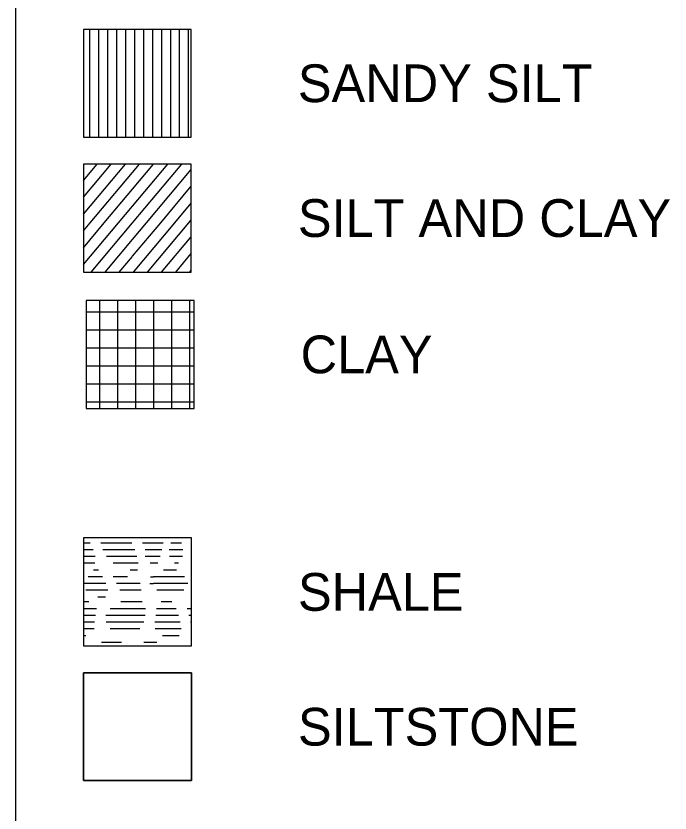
# Model space of a CAD drawing. Extents: x -60 to 375, y -195 to 44.
# Drawn here: x 6.309 to 7.521, y 8.242 to 9.72 of the extents above; entities that cross this region are included whole.
import ezdxf

# ---------------------------------------------------------------- set-up
doc = ezdxf.new("R2010")
doc.units = 0
for name, color, linetype in [('GM_X_County', 7, 'Continuous'), ('GM_X_Minor_Lake_Text', 7, 'Continuous'), ('GM_X_Minor_River_Text', 7, 'Continuous')]:
    doc.layers.add(name, color=color, linetype=linetype)

msp = doc.modelspace()

# ---------------------------------------------------------------- linework, layer by layer
at = {"layer": 'GM_X_Minor_Lake_Text'}
msp.add_line((6.3089, 5.5693), (6.3089, 10.7192), dxfattribs=at)
for points in [[(6.4339, 9.4954), (6.6339, 9.4954), (6.6339, 9.6954), (6.4339, 9.6954)], [(6.4339, 9.2454), (6.6339, 9.2454), (6.6339, 9.4454), (6.4339, 9.4454)], [(6.439, 8.9926), (6.639, 8.9926), (6.639, 9.1926), (6.439, 9.1926)], [(6.4341, 8.5522), (6.6341, 8.5522), (6.6341, 8.7522), (6.4341, 8.7522)], [(6.4341, 8.3022), (6.6341, 8.3022), (6.6341, 8.5022), (6.4341, 8.5022)]]:
    msp.add_lwpolyline(points, close=True, dxfattribs=at)
at = {"layer": 'GM_X_Minor_River_Text'}
for p, q in [((6.4457, 9.5985), (6.4457, 9.6954)), ((6.4623, 9.5985), (6.4623, 9.6954)), ((6.479, 9.5985), (6.479, 9.6954)), ((6.4957, 9.5985), (6.4957, 9.6954)), ((6.5123, 9.5985), (6.5123, 9.6954)), ((6.529, 9.5985), (6.529, 9.6954)), ((6.5457, 9.5985), (6.5457, 9.6954)), ((6.5623, 9.5985), (6.5623, 9.6954)), ((6.579, 9.5985), (6.579, 9.6954)), ((6.5957, 9.5985), (6.5957, 9.6954)), ((6.6123, 9.5985), (6.6123, 9.6954)), ((6.629, 9.5985), (6.629, 9.6954)), ((6.6335, 9.5948), (6.6335, 9.6954)), ((6.4457, 9.4954), (6.4457, 9.5985)), ((6.4623, 9.4954), (6.4623, 9.5985)), ((6.479, 9.4954), (6.479, 9.5985)), ((6.4957, 9.4954), (6.4957, 9.5985)), ((6.5123, 9.4954), (6.5123, 9.5985)), ((6.529, 9.4954), (6.529, 9.5985)), ((6.5457, 9.4954), (6.5457, 9.5985)), ((6.5623, 9.4954), (6.5623, 9.5985)), ((6.579, 9.4954), (6.579, 9.5985)), ((6.5957, 9.4954), (6.5957, 9.5985)), ((6.6123, 9.4954), (6.6123, 9.5985)), ((6.629, 9.4954), (6.629, 9.5985)), ((6.6335, 9.4954), (6.6335, 9.5948)), ((6.4339, 9.415), (6.4595, 9.4454)), ((6.4339, 9.3839), (6.4856, 9.4454)), ((6.4339, 9.3527), (6.5117, 9.4454)), ((6.5249, 9.4299), (6.5379, 9.4454)), ((6.5249, 9.3988), (6.564, 9.4454)), ((6.5249, 9.3677), (6.5901, 9.4454)), ((6.525, 9.3367), (6.6162, 9.4454)), ((6.5511, 9.3367), (6.6339, 9.4354)), ((6.4466, 9.3367), (6.5248, 9.4299)), ((6.5772, 9.3367), (6.6339, 9.4043)), ((6.4727, 9.3367), (6.5248, 9.3988)), ((6.6033, 9.3367), (6.6339, 9.3732)), ((6.4988, 9.3367), (6.5248, 9.3677)), ((6.6294, 9.3367), (6.6339, 9.3421)), ((6.4339, 9.3216), (6.4466, 9.3367)), ((6.4339, 9.2905), (6.4727, 9.3367)), ((6.4339, 9.2594), (6.4988, 9.3367)), ((6.4483, 9.2454), (6.5249, 9.3367)), ((6.525, 9.2745), (6.5772, 9.3367)), ((6.525, 9.3056), (6.5511, 9.3367)), ((6.5267, 9.2454), (6.6033, 9.3367)), ((6.5528, 9.2454), (6.6294, 9.3367)), ((6.4744, 9.2454), (6.5248, 9.3055)), ((6.5789, 9.2454), (6.6339, 9.3109)), ((6.5005, 9.2454), (6.5248, 9.2744)), ((6.605, 9.2454), (6.6339, 9.2798)), ((6.6311, 9.2454), (6.6339, 9.2487)), ((6.4645, 9.0882), (6.4645, 9.1926)), ((6.4978, 9.0882), (6.4978, 9.1926)), ((6.5311, 9.0882), (6.5311, 9.1926)), ((6.5645, 9.0882), (6.5645, 9.1926)), ((6.5978, 9.0882), (6.5978, 9.1926)), ((6.6311, 9.0882), (6.6311, 9.1926)), ((6.439, 9.1715), (6.5145, 9.1715)), ((6.5145, 9.1715), (6.639, 9.1715)), ((6.439, 9.1381), (6.5145, 9.1381)), ((6.5145, 9.1381), (6.639, 9.1381)), ((6.439, 9.1048), (6.5145, 9.1048)), ((6.5145, 9.1048), (6.639, 9.1048)), ((6.4645, 8.9926), (6.4645, 9.0882)), ((6.4978, 8.9926), (6.4978, 9.0882)), ((6.5311, 8.9926), (6.5311, 9.0882)), ((6.5645, 8.9926), (6.5645, 9.0882)), ((6.5978, 8.9926), (6.5978, 9.0882)), ((6.6311, 8.9926), (6.6311, 9.0882)), ((6.439, 9.0715), (6.5145, 9.0715)), ((6.5145, 9.0715), (6.639, 9.0715)), ((6.439, 9.0381), (6.5145, 9.0381)), ((6.5145, 9.0381), (6.639, 9.0381)), ((6.439, 9.0048), (6.5145, 9.0048)), ((6.5145, 9.0048), (6.639, 9.0048)), ((6.4463, 8.7427), (6.4341, 8.7427)), ((6.5235, 8.7427), (6.466, 8.7427)), ((6.564, 8.7427), (6.5433, 8.7427)), ((6.5818, 8.7427), (6.564, 8.7427)), ((6.6159, 8.7427), (6.5962, 8.7427)), ((6.4521, 8.7302), (6.4341, 8.7302)), ((6.5292, 8.7302), (6.47, 8.7302)), ((6.564, 8.7302), (6.5481, 8.7302)), ((6.5791, 8.7302), (6.564, 8.7302)), ((6.6184, 8.7302), (6.593, 8.7302)), ((6.456, 8.7177), (6.4341, 8.7177)), ((6.5331, 8.7177), (6.4766, 8.7177)), ((6.564, 8.7177), (6.5482, 8.7177)), ((6.5763, 8.7177), (6.564, 8.7177)), ((6.6175, 8.7177), (6.5933, 8.7177)), ((6.4553, 8.7052), (6.4341, 8.7052)), ((6.4619, 8.6927), (6.4524, 8.6927)), ((6.5353, 8.7052), (6.4888, 8.7052)), ((6.5341, 8.6927), (6.5209, 8.6927)), ((6.564, 8.7052), (6.5578, 8.7052)), ((6.5719, 8.7052), (6.564, 8.7052)), ((6.6062, 8.6927), (6.5822, 8.6927)), ((6.61, 8.7052), (6.6025, 8.7052)), ((6.4691, 8.6802), (6.4428, 8.6802)), ((6.5158, 8.6802), (6.4891, 8.6802)), ((6.5584, 8.6802), (6.564, 8.6802)), ((6.621, 8.6802), (6.564, 8.6802)), ((6.4755, 8.6677), (6.4341, 8.6677)), ((6.5393, 8.6677), (6.4952, 8.6677)), ((6.5568, 8.6677), (6.564, 8.6677)), ((6.6275, 8.6677), (6.564, 8.6677)), ((6.4789, 8.6552), (6.4385, 8.6552)), ((6.5408, 8.6552), (6.5016, 8.6552)), ((6.6201, 8.6552), (6.5703, 8.6552)), ((6.4441, 8.6335), (6.4341, 8.6335)), ((6.475, 8.6427), (6.4604, 8.6427)), ((6.5427, 8.6335), (6.5035, 8.6335)), ((6.5977, 8.6335), (6.5783, 8.6335)), ((6.4582, 8.621), (6.4341, 8.621)), ((6.549, 8.621), (6.4836, 8.621)), ((6.606, 8.621), (6.5694, 8.621)), ((6.6341, 8.621), (6.6261, 8.621)), ((6.4564, 8.6085), (6.4341, 8.6085)), ((6.5486, 8.6085), (6.4758, 8.6085)), ((6.6099, 8.6085), (6.5682, 8.6085)), ((6.6341, 8.6085), (6.6295, 8.6085)), ((6.4545, 8.596), (6.4341, 8.596)), ((6.546, 8.596), (6.4762, 8.596)), ((6.6131, 8.596), (6.5666, 8.596)), ((6.6341, 8.596), (6.6324, 8.596)), ((6.4537, 8.5835), (6.4341, 8.5835)), ((6.5386, 8.5835), (6.4834, 8.5835)), ((6.615, 8.5835), (6.5668, 8.5835)), ((6.6341, 8.5835), (6.6334, 8.5835)), ((6.4386, 8.571), (6.4341, 8.571)), ((6.5048, 8.5585), (6.4676, 8.5585)), ((6.564, 8.5585), (6.546, 8.5585)), ((6.57, 8.5585), (6.564, 8.5585)), ((6.6115, 8.571), (6.5807, 8.571))]:
    msp.add_line(p, q, dxfattribs=at)
msp.add_lwpolyline([(6.4341, 8.5022), (6.6341, 8.5022), (6.6341, 8.3022), (6.4341, 8.3022)], close=True, dxfattribs=at)

# ---------------------------------------------------------------- texts
at = {"layer": 'GM_X_County'}
for s, p in [('SANDY SILT', (6.8314, 9.5604)), ('SILT AND CLAY', (6.8314, 9.3104)), ('CLAY', (6.8365, 9.0576)), ('SHALE', (6.8316, 8.6172)), ('SILTSTONE', (6.8316, 8.3672))]:
    msp.add_text(s, height=0.07, dxfattribs=at).set_placement(p)

doc.saveas('drawing.dxf')
